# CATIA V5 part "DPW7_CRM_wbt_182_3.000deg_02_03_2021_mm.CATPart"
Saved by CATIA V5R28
Part number: DPW7_CRM_wbt_182_2.995deg_02_03_2021
Bounding box of the stored display mesh (mm): x 2349.5 to 66711.891, y 0 to 29456.883, z 2310.119 to 8715.756
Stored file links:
  Z:\Scratch\04_CAD_Allgemein\Flight2Jig\Output\DPW-7\CATPart\DPW7_CRM_wbt_182_2.995deg_02_03_2021.CATPart
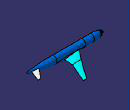
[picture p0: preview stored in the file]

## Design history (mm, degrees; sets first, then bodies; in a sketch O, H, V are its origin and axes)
Set1
  DatumSurface1 "Clean_Wing"
  DatumSurface2 "Fuselage"
  DatumSurface3 "HTP"
  DatumSurface4 "Symmetry"
  DatumSurface5 "Farfield"
Body1 (main body)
